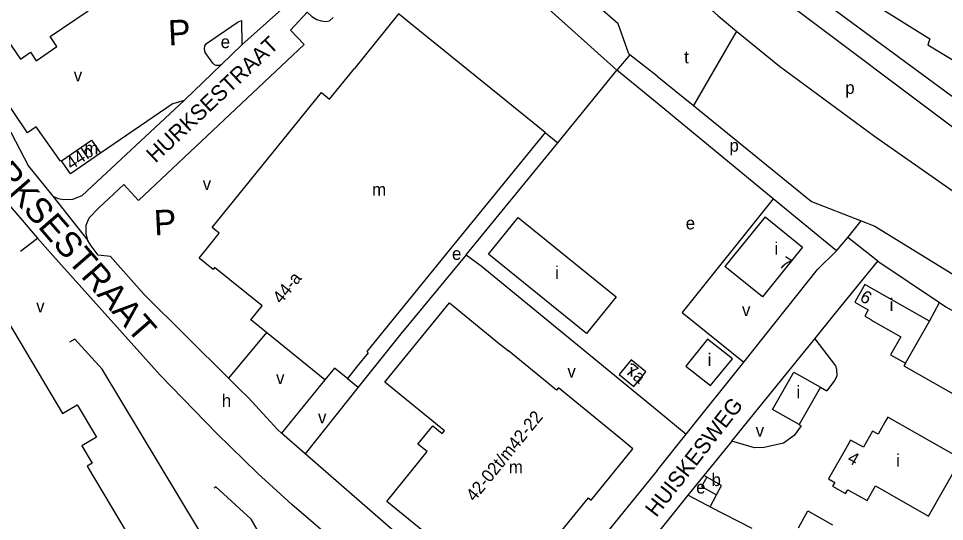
# Model space of a CAD drawing. Extents: x 157699 to 159683, y 381451 to 383293.
# Drawn here: x 157847.3 to 158141.2, y 382912.1 to 383071.8 of the extents above; entities that cross this region are included whole.
import ezdxf

# ---------------------------------------------------------------- set-up
doc = ezdxf.new("R2010")
doc.units = 0
for name, color, linetype in [('BLT_Basislijn', 7, 'Continuous'), ('BLT_Bebouwing', 7, 'Continuous'), ('BLT_Centroide', 7, 'Continuous'), ('BLT_Huisnummer', 7, 'Continuous'), ('BLT_Huisnummer_reeks', 7, 'Continuous'), ('BLT_Straatnaam', 7, 'Continuous'), ('BLT_Straatnaam_hoofdweg', 7, 'Continuous'), ('BLT_Tekst_parkeren', 7, 'Continuous'), ('BLT_Vlakafsluiter', 7, 'Continuous')]:
    doc.layers.add(name, color=color, linetype=linetype)

msp = doc.modelspace()

# ---------------------------------------------------------------- linework, layer by layer
at = {"layer": 'BLT_Basislijn'}
for p, q in [((158037.28, 383055.35), (157982.22, 383104.82)), ((158086.23, 383080.66), (158151.95, 383031.19)), ((157918.26, 383063.41), (157933.88, 383077.4)), ((157918.26, 383063.41), (157911.73, 383057.24)), ((158041.42, 383060.3), (158037.28, 383055.35)), ((157900.05, 383045.82), (157911.73, 383057.24)), ((158033.78, 383051.08), (158037.28, 383055.35)), ((158050, 383044.87), (158037.28, 383055.35)), ((158018.48, 383032.33), (158033.78, 383051.08)), ((157896.41, 383044.86), (157873.33, 383029.01)), ((157896.41, 383044.86), (157900.05, 383045.82)), ((158086.92, 383014.49), (158050, 383044.87)), ((158014.48, 383035.58), (158018.48, 383032.33)), ((157989.46, 382996.75), (158018.48, 383032.33)), ((158106.97, 382997.99), (158086.92, 383014.49)), ((157844.49, 383012.38), (157849.12, 383007.02)), ((158110.57, 383002.24), (158114.78, 383007.56)), ((157847.97, 382997.93), (157853.38, 383002.06)), ((158106.97, 382997.99), (158110.57, 383002.24)), ((158120.11, 382994.79), (158110.57, 383002.24)), ((158106.97, 382997.99), (158100.98, 382992.11)), ((158106.1, 382977.59), (158120.11, 382994.79)), ((158120.11, 382994.79), (158139.65, 382981.65)), ((158077.53, 382962.7), (158100.98, 382992.11)), ((158136.48, 382975.73), (158139.65, 382981.65)), ((158100.1, 382970.13), (158106.1, 382977.59)), ((157926.01, 382972.15), (157913.98, 382957.57)), ((158059.28, 382939.8), (158077.53, 382962.7)), ((157917.43, 382954.14), (157913.98, 382957.57)), ((157944.6, 382957.08), (157930.82, 382940.17)), ((157951.72, 382957.5), (157955.16, 382954.71)), ((157920.25, 382951.41), (157917.43, 382954.14)), ((158101.91, 382954.7), (158103.95, 382953.59)), ((158050, 382947.43), (158059.28, 382939.8)), ((157938.29, 382933.57), (157930.82, 382940.17)), ((158095.15, 382942.84), (158095.8, 382942.49)), ((158050, 382928.32), (158059.28, 382939.8)), ((158073.71, 382937.62), (158064.86, 382926.69)), ((158064.86, 382926.69), (158059.8, 382920.44)), ((158065.77, 382926.17), (158064.86, 382926.69)), ((158059.8, 382920.44), (158050, 382908.32)), ((158066.82, 382916.77), (158068.87, 382920.52)), ((158066.82, 382916.77), (158080.06, 382909.99))]:
    msp.add_line(p, q, dxfattribs=at)
for points in [[(158041.42, 383060.3), (158041.02, 383060.62), (158037.71, 383070.13), (158027.85, 383078.82), (158014.42, 383091.59)], [(158050, 383090.06), (158069.37, 383072.64), (158075.25, 383067.82)], [(158253.94, 382986.99), (158231.51, 382996.79), (158211.77, 383006.78), (158182.9, 383022.33), (158161.49, 383035.3), (158143.35, 383047.24), (158099.36, 383079.76), (158098.12, 383081.44), (158097.48, 383083.34), (158097.64, 383085.35), (158098.03, 383086.17)], [(157872.79, 383011.68), (157880.74, 383019.11), (157885.38, 383014.04), (157938.05, 383063.51), (157933.67, 383068.11), (157938.93, 383073.83)], [(157938.93, 383073.83), (157940.43, 383072.46), (157942.03, 383071.53), (157943.42, 383071.03), (157944.88, 383070.9), (157946.08, 383071.04), (157947.22, 383072.13)], [(157911.73, 383057.24), (157911.09, 383056.89), (157910.03, 383056.86), (157909.51, 383057.09), (157908.99, 383057.58), (157906.61, 383061.05), (157906.35, 383062.12), (157906.49, 383063.13), (157907.04, 383063.88), (157917.07, 383070.71), (157918.14, 383071.18), (157918.26, 383063.41)], [(157860.92, 383026.64), (157860.67, 383026.47), (157852.89, 383037.45), (157850.23, 383035.52), (157827.41, 383069.11)], [(158075.25, 383067.82), (158088.9, 383056.64), (158119.01, 383034.47), (158143.64, 383017.24)], [(158050, 383053.52), (158041.42, 383060.3)], [(157829.27, 383054.04), (157845.02, 383035.53), (157850.52, 383024.91), (157858.19, 383015.35)], [(158050, 383053.52), (158061.54, 383044.13)], [(157867.53, 383015.61), (157900.05, 383045.82)], [(158061.54, 383044.13), (158099.02, 383013.66), (158114.78, 383007.56)], [(157858.19, 383015.35), (157859.87, 383014.61), (157861.73, 383014.32), (157864.53, 383014.39), (157867.53, 383015.61)], [(158086.92, 383014.49), (158057.95, 382978.45), (158077.53, 382962.7)], [(157869.3, 383001.36), (157868.75, 383003.49), (157868.75, 383006.14), (157869.72, 383008.47), (157872.79, 383011.68)], [(157849.12, 383007.02), (157851.34, 383004.42), (157853.38, 383002.06)], [(158114.78, 383007.56), (158119.11, 383005.88), (158153.03, 382984.99)], [(157949.07, 382904.54), (157934.04, 382917.51), (157923.29, 382927.29), (157910.32, 382940.07), (157892.3, 382958.54), (157858.2, 382996.52), (157853.38, 383002.06)], [(157876.57, 382996.24), (157872.61, 382996.69), (157870.37, 382999.65), (157869.3, 383001.36)], [(157913.98, 382957.57), (157887.19, 382984.16), (157876.57, 382996.24)], [(157989.46, 382996.75), (157968.65, 382971.63), (157955.16, 382954.71)], [(157989.46, 382996.75), (157994.23, 382993.29), (158050, 382947.43)], [(158139.65, 382981.65), (158141.72, 382980.26), (158178.15, 382959.62)], [(157916.6, 382889.41), (157873.89, 382960.49), (157865.17, 382970), (157863.48, 382969.01)], [(158073.71, 382937.62), (158080.93, 382946.51), (158083.67, 382949.89), (158100.1, 382970.13)], [(158100.1, 382970.13), (158106.65, 382961.49), (158107.01, 382960.41), (158107.07, 382958.22), (158106.33, 382956.84), (158103.95, 382953.59)], [(158128.86, 382962.33), (158128.37, 382961.46), (158202.8, 382919.14)], [(157955.16, 382954.71), (157938.29, 382933.57)], [(157930.82, 382940.17), (157929.67, 382941.19), (157920.25, 382951.41)], [(158095.8, 382942.49), (158093.55, 382939.43), (158090.1, 382936.97), (158084.03, 382935.54), (158080.93, 382935.46), (158073.71, 382937.62)], [(158004.65, 382879.91), (157977.9, 382900), (157966.26, 382909.27), (157938.29, 382933.57)], [(158050, 382928.32), (158027.13, 382900), (158011.79, 382880.82), (158010.52, 382879.91), (158008.17, 382879.17), (158006.02, 382879.33), (158004.65, 382879.91)], [(157927.35, 382902.27), (157921.19, 382912.79), (157910, 382923.04), (157909.38, 382922.68)], [(158066.82, 382916.77), (158066.05, 382917.17), (158059.8, 382920.44)]]:
    msp.add_lwpolyline(points, dxfattribs=at)
at = {"layer": 'BLT_Bebouwing'}
for p, q in [((157967.98, 383073.26), (157953.94, 383055.93)), ((158084.31, 383008.84), (158071.51, 382993.04)), ((158084.31, 383008.84), (158096.22, 382999.2)), ((158128.86, 382962.33), (158136.48, 382975.73)), ((157944.6, 382957.08), (157926.01, 382972.15)), ((158018.12, 382953.76), (158002.83, 382966.23)), ((158101.91, 382954.7), (158095.15, 382942.84)), ((158070.52, 382923.56), (158065.77, 382926.17)), ((158068.87, 382920.52), (158070.52, 382923.56))]:
    msp.add_line(p, q, dxfattribs=at)
for points in [[(158124.98, 383118.41), (158112.95, 383080.12), (158136.6, 383065.4), (158135.98, 383063.43)], [(157836.87, 383074.96), (157847.92, 383058.94), (157851.08, 383061.12), (157852.92, 383058.41), (157859.51, 383062.96), (157857.36, 383066.06), (157869.39, 383074.29)], [(158014.48, 383035.58), (158000, 383047.32), (157971.87, 383070.11), (157968.86, 383072.55), (157967.98, 383073.26)], [(158135.98, 383063.43), (158159.73, 383049.09), (158159.29, 383047.71)], [(157926.01, 382972.15), (157921.1, 382976.13), (157924.66, 382980.53), (157909.58, 382992.76), (157909.08, 382992.14), (157904.65, 382995.73), (157908.11, 383000), (157911.06, 383003.64), (157908.8, 383005.47), (157943.51, 383048.3), (157946.07, 383046.22), (157953.94, 383055.93)], [(158014.48, 383035.58), (157985.52, 383000), (157957.89, 382966.07), (157958.36, 382965.69), (157954.87, 382961.38), (157951.72, 382957.5)], [(157860.92, 383026.64), (157870.53, 383033.17), (157873.33, 383029.01)], [(157873.33, 383029.01), (157863.8, 383022.47), (157860.92, 383026.64)], [(158096.22, 382999.2), (158083.43, 382983.39), (158071.51, 382993.04)], [(158136.48, 382975.73), (158115.93, 382987.37), (158112.74, 382981.71)], [(157837.7, 382985.98), (157861.29, 382946.4), (157865.96, 382949.15), (157872.1, 382938.88), (157867.46, 382936.08), (157870.72, 382930.6), (157869.09, 382929.61), (157892.34, 382890.7)], [(157982.5, 382940.9), (157963.58, 382956.31), (157966.74, 382960.19), (157984.1, 382981.49), (158000, 382968.53), (158002.83, 382966.23)], [(158112.74, 382981.71), (158117.05, 382979.3), (158115.94, 382977.33), (158117.9, 382976.22), (158117.83, 382976.09), (158127.35, 382970.7), (158124.12, 382965.02), (158128.86, 382962.33)], [(157951.72, 382957.5), (157947.64, 382960.82), (157944.6, 382957.08)], [(158095.15, 382942.84), (158086.63, 382947.65), (158093.39, 382959.53), (158101.91, 382954.7)], [(158028.13, 382919.64), (158029.06, 382918.9), (158042.35, 382935.2), (158038.48, 382938.36), (158018.71, 382954.49), (158018.12, 382953.76)], [(158122.34, 382943.66), (158120.16, 382939.81), (158118.44, 382940.8), (158115.53, 382935.69)], [(158119.33, 382923.36), (158136.2, 382913.77), (158146.55, 382931.95), (158123.22, 382945.2), (158122.34, 382943.66)], [(157980.27, 382906.59), (157979.68, 382905.87), (157964.22, 382918.47), (157977.09, 382934.26), (157974.11, 382936.69), (157978.79, 382942.44), (157981.77, 382940), (157982.5, 382940.9)], [(158115.53, 382935.69), (158111.41, 382937.9), (158109.78, 382935.01)], [(158109.78, 382935.01), (158104.46, 382925.64), (158106.41, 382924.49), (158105.74, 382923.29), (158109.84, 382920.97), (158110.55, 382922.18), (158116.67, 382918.72), (158119.33, 382923.36)], [(158065.77, 382926.17), (158064.11, 382923.2), (158068.87, 382920.52)], [(158028.13, 382919.64), (158012.17, 382900), (158002.62, 382888.25), (158000, 382890.4), (157988.3, 382900), (157980.27, 382906.59)], [(158094.87, 382910.08), (158097.9, 382915.45), (158105.74, 382911.03)]]:
    msp.add_lwpolyline(points, dxfattribs=at)
for points in [[(157996.5, 382996.98), (158005.93, 383008.64), (158036.98, 382983.39), (158027.58, 382971.77)], [(158059.13, 382961.43), (158066.94, 382955.24), (158073.91, 382963.7), (158066.04, 382969.94)], [(158046.46, 382959.66), (158041.81, 382963.42), (158038.01, 382958.8), (158042.63, 382955)]]:
    msp.add_lwpolyline(points, close=True, dxfattribs=at)
at = {"layer": 'BLT_Vlakafsluiter'}
for p, q in [((158075.25, 383067.82), (158061.54, 383044.13)), ((157858.19, 383015.35), (157869.3, 383001.36))]:
    msp.add_line(p, q, dxfattribs=at)

# ---------------------------------------------------------------- texts
at = {"layer": 'BLT_Centroide'}
for s, p in [('e', (157911.5, 383062.4)), ('t', (158058.63, 383057.56)), ('v', (157864.86, 383051.82)), ('p', (158109.75, 383047.86)), ('m', (157868.23, 383028.64)), ('p', (158072.99, 383029.51)), ('v', (157905.79, 383017.37)), ('m', (157959.56, 383015.5)), ('e', (158059.12, 383004.83)), ('i', (158087.28, 382996.77)), ('e', (157984.92, 382995.16)), ('i', (158017.67, 382989.13)), ('v', (157852.93, 382978.52)), ('i', (158123.83, 382978.94)), ('v', (158076.97, 382977.32)), ('i', (158066.06, 382961.45)), ('v', (158021.55, 382957.8)), ('i', (158041.3, 382958.08)), ('v', (157929.08, 382955.74)), ('i', (158094.27, 382951.19)), ('h', (157911.85, 382948.47)), ('v', (157942.4, 382943.24)), ('v', (158081.32, 382939)), ('i', (158125.9, 382929.5)), ('m', (158002.97, 382927.41)), ('b', (158067.3, 382923.34)), ('e', (158062.42, 382920.96))]:
    msp.add_text(s, height=4, dxfattribs=at).set_placement(p)
at = {"layer": 'BLT_Huisnummer'}
for s, rotation, p in [('44b', 34.2491, (157864.12, 383023.61)), ('7', 326.503, (158088.46, 382993.21)), ('6', 330.6644, (158114.1, 382982.31)), ('7a', 321.503, (158039.68, 382959.37)), ('4', 330.6765, (158110.11, 382931.13))]:
    msp.add_text(s, height=4, rotation=rotation, dxfattribs=at).set_placement(p)
at = {"layer": 'BLT_Huisnummer_reeks'}
for s, rotation, p in [('44-a', 50.9825, (157930.7, 382980.96)), ('42-02t/m42-22', 50.8978, (157992.06, 382918.19))]:
    msp.add_text(s, height=4, rotation=rotation, dxfattribs=at).set_placement(p)
at = {"layer": 'BLT_Straatnaam'}
for s, rotation, p in [('HURKSESTRAAT', 43.3051, (157890.79, 383025.72)), ('HUISKESWEG', 52.1086, (158049.76, 382913.19))]:
    msp.add_text(s, height=5, rotation=rotation, dxfattribs=at).set_placement(p)
at = {"layer": 'BLT_Straatnaam_hoofdweg'}
msp.add_text('HURKSESTRAAT', height=8, rotation=311.0051, dxfattribs=at).set_placement((157828.67, 383033.86))
at = {"layer": 'BLT_Tekst_parkeren'}
for p in [(157895.01, 383063.23), (157890.49, 383002.93)]:
    msp.add_text('P', height=8, rotation=2.8586, dxfattribs=at).set_placement(p)

doc.saveas('drawing.dxf')
